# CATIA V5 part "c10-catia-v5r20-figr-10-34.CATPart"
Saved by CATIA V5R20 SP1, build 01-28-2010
Part number: Part1
Bounding box of the stored display mesh (mm): x 0 to 100, y -43.492 to 31.433, z -3.653 to 11.537
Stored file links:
  D:\v5_r20\psrt_files_downloaded\c10\c10-catia-v5r20-figr-10-34.CATPart
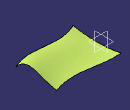
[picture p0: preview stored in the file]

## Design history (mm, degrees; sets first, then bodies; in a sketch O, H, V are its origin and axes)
Set1
  Sketch1 on yz-plane, origin (0, 0, 0), H (0, 1, 0), V (0, 0, 1)
  Plane1: type Offset, RefPlane yz-plane, Offset 100
  Sketch2 on xy-plane, origin (0, 0, 0), H (1, 0, 0), V (0, 1, 0)
    spline S1 through (0, 31.0443) (19.7053, 31.0443) (51.809, 26.4574) (100, 31.0443)
    reference intersected line E1 through (100, 0) direction (0, 1) from Plane1
    point P1 (0, 31.0443)
    point P2 (100, 31.0443)
    coincidence: P1 V, P2 E1
  Sketch3 on xy-plane, origin (0, 0, 0), H (1, 0, 0), V (0, 1, 0)
    spline S1 through (0, -43.492) (26.209, -36.2295) (80.3728, -38.1407) (100, -32.0249)
    reference intersected line E1 through (100, 0) direction (0, 1) from Plane1
    point P1 (0, -43.492)
    point P2 (100, -32.0249)
    coincidence: P1 V, P2 E1
  Sketch4 on Plane1, origin (100, 0, 0), H (0, 1, 0), V (0, 0, 1)
    spline S1 through (-32.0249, 0) (-14.5305, 11.3827) (11.9668, 5.3652) (31.0443, 0)
    reference projected point E1 (31.0443, 0) from vertex of Sketch2
    reference projected point E2 (-32.0249, 0) from vertex of Sketch3
    point P1 (-32.0249, 0)
    point P2 (31.0443, 0)
    coincidence: P1 H, P2 H, P2 E1, P1 E2
  Sketch5 on yz-plane, origin (0, 0, 0), H (0, 1, 0), V (0, 0, 1)
    spline S1 through (31.0443, 0) (7.4727, -3.1675) (-43.492, 0)
    reference projected point E1 (-43.492, 0) from vertex of Sketch3
    reference projected point E2 (31.0443, 0) from vertex of Sketch2
    point P1 (31.0443, 0)
    point P2 (-43.492, 0)
    coincidence: P1 H, P2 H, P2 E1, P1 E2
  Fill1: Boundary (Sketch5; Sketch3; Sketch4; Sketch2)
Body1 (main body)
